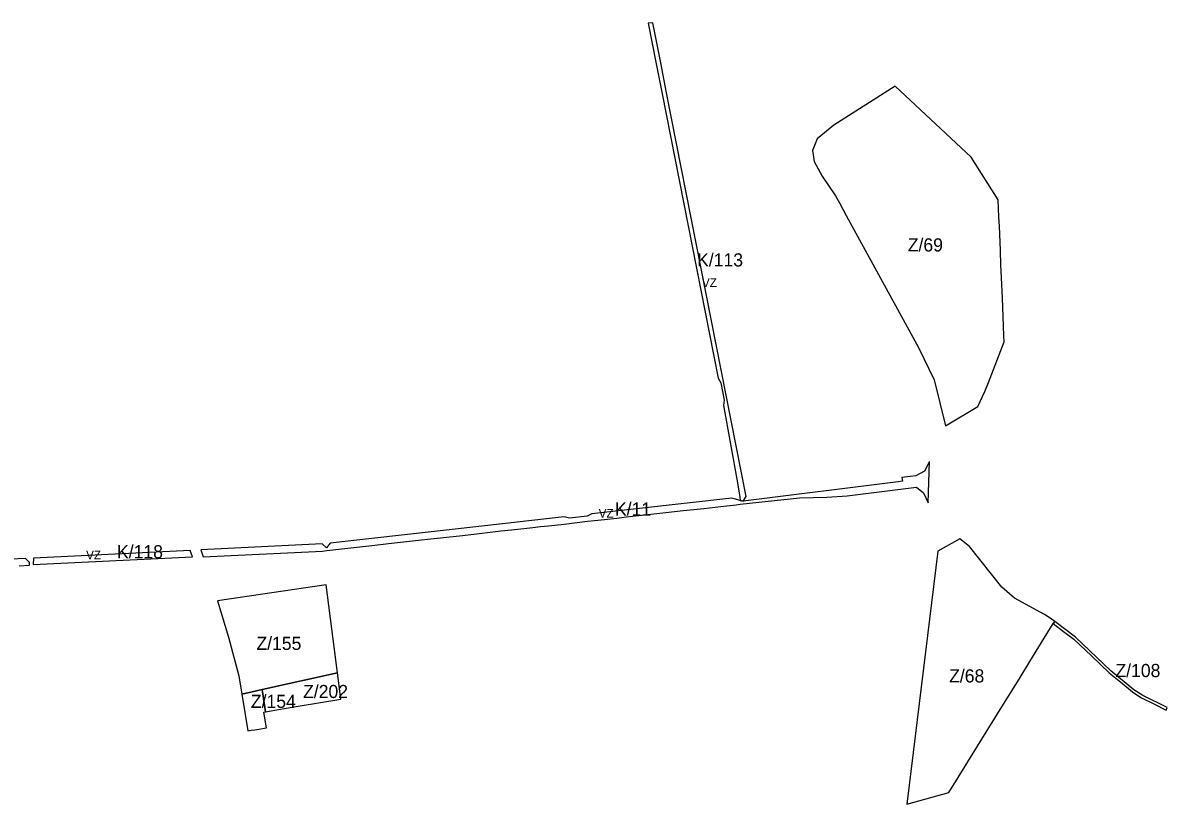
# Model space of a CAD drawing. Extents: x -521939 to -518034, y -1194984 to -1189555.
# Drawn here: x -519696 to -518391, y -1190882 to -1189991 of the extents above; entities that cross this region are included whole.
import ezdxf

# ---------------------------------------------------------------- set-up
doc = ezdxf.new("R2010")
doc.units = 0
for name, color, linetype in [('95420023', 7, 'Continuous'), ('96111023', 7, 'Continuous'), ('96202223', 7, 'Continuous')]:
    doc.layers.add(name, color=color, linetype=linetype)

msp = doc.modelspace()

# ---------------------------------------------------------------- linework, layer by layer
at = {"layer": '95420023'}
for points in [[(-518700.81, -1190062.95), (-518770.96, -1190107.15)], [(-518583.4, -1190192.5), (-518614.2, -1190143.77), (-518700.81, -1190062.95)], [(-518770.96, -1190107.15), (-518790.08, -1190122.73), (-518795.26, -1190136.18)], [(-518795.26, -1190136.18), (-518793.36, -1190148.8)], [(-518793.36, -1190148.8), (-518784.15, -1190165.5)], [(-518784.15, -1190165.5), (-518769.16, -1190188.04)], [(-518769.16, -1190188.04), (-518764.54, -1190195.99), (-518757.02, -1190210.42)], [(-518582.56, -1190212.26), (-518583.4, -1190192.5)], [(-518757.02, -1190210.42), (-518674.29, -1190361.03)], [(-518582.12, -1190222.61), (-518582.56, -1190212.26)], [(-518580.95, -1190250.13), (-518582.12, -1190222.61)], [(-518580.25, -1190266.63), (-518580.95, -1190250.13)], [(-518579.59, -1190281.03), (-518580.25, -1190266.63)], [(-518578.63, -1190304.8), (-518579.59, -1190281.03)], [(-518577.28, -1190336.35), (-518578.63, -1190304.8)], [(-518576.83, -1190347.45), (-518577.28, -1190336.35)], [(-518594.44, -1190400.79), (-518576.52, -1190354.3)], [(-518576.52, -1190354.3), (-518576.83, -1190347.45)], [(-518674.29, -1190361.03), (-518656.44, -1190397.83)], [(-518656.44, -1190397.83), (-518643.4, -1190450.09)], [(-518606.61, -1190428.32), (-518598.55, -1190411.07)], [(-518598.55, -1190411.07), (-518594.44, -1190400.79)], [(-518643.4, -1190450.09), (-518606.61, -1190428.32)], [(-518627.12, -1190579.12), (-518652.45, -1190593.34), (-518687.6, -1190881.68)], [(-518616.2, -1190587.89), (-518627.12, -1190579.12)], [(-518579.17, -1190634.29), (-518616.2, -1190587.89)], [(-519350.06, -1190631.54), (-519474.2, -1190649.71)], [(-519337.21, -1190732.05), (-519348.65, -1190643.36), (-519350.06, -1190631.54)], [(-518564.68, -1190646.91), (-518579.17, -1190634.29)], [(-518520.61, -1190672.06), (-518530.66, -1190665.45), (-518564.68, -1190646.91)], [(-519474.2, -1190649.71), (-519461.43, -1190691.22), (-519449.61, -1190735.43), (-519446.26, -1190756.2)], [(-518518.98, -1190673.29), (-518520.61, -1190672.06)], [(-518547.39, -1190719.17), (-518520.57, -1190675.85)], [(-518520.57, -1190675.85), (-518518.98, -1190673.29)], [(-518518.98, -1190673.29), (-518520.57, -1190675.85)], [(-518520.57, -1190675.85), (-518508.82, -1190684.74)], [(-518495.13, -1190691.35), (-518518.98, -1190673.29)], [(-518508.82, -1190684.74), (-518497.07, -1190693.64), (-518476.92, -1190712.71)], [(-518454.79, -1190729.54), (-518495.13, -1190691.35)], [(-518629.18, -1190851.22), (-518607.03, -1190815.46), (-518584.36, -1190778.86), (-518558.52, -1190737.14), (-518547.39, -1190719.17)], [(-518476.92, -1190712.71), (-518456.78, -1190731.79), (-518443.59, -1190742.68), (-518430.41, -1190753.58)], [(-519423.08, -1190751.07), (-519337.21, -1190732.05)], [(-519337.21, -1190732.05), (-519423.08, -1190751.07)], [(-519333.43, -1190761.83), (-519337.21, -1190732.05)], [(-518418.46, -1190757.75), (-518428.63, -1190751.16), (-518454.79, -1190729.54)], [(-519423.08, -1190751.07), (-519434.67, -1190753.64), (-519446.26, -1190756.2)], [(-519446.26, -1190756.2), (-519434.67, -1190753.64), (-519423.08, -1190751.07)], [(-519419.09, -1190776.27), (-519423.08, -1190751.07)], [(-519423.08, -1190751.07), (-519419.09, -1190776.27)], [(-519446.26, -1190756.2), (-519439.5, -1190798.18)], [(-519381.92, -1190770.01), (-519333.43, -1190761.83)], [(-518430.41, -1190753.58), (-518425.18, -1190756.97), (-518419.95, -1190760.36)], [(-518419.95, -1190760.36), (-518405.94, -1190767.38)], [(-518390.75, -1190771.64), (-518418.46, -1190757.75)], [(-519418.25, -1190794.59), (-519421.35, -1190776.66), (-519419.09, -1190776.27)], [(-519419.09, -1190776.27), (-519402.04, -1190773.36)], [(-519402.04, -1190773.36), (-519397.85, -1190772.66)], [(-519397.85, -1190772.66), (-519381.92, -1190770.01)], [(-518405.94, -1190767.38), (-518391.94, -1190774.4), (-518390.75, -1190771.64)], [(-519439.5, -1190798.18), (-519435.5, -1190797.51)], [(-519435.5, -1190797.51), (-519431.49, -1190796.83)], [(-519431.49, -1190796.83), (-519427.06, -1190796.08), (-519418.25, -1190794.59)], [(-518639.88, -1190868.49), (-518629.18, -1190851.22)], [(-518687.6, -1190881.68), (-518639.88, -1190868.49)]]:
    msp.add_lwpolyline(points, dxfattribs=at)
at = {"layer": '96111023'}
for points in [[(-518977.46, -1189990.66), (-518982.75, -1189991.08)], [(-518982.75, -1189991.08), (-518973.66, -1190037.25)], [(-518968.46, -1190036.36), (-518977.46, -1189990.66)], [(-518973.66, -1190037.25), (-518966.93, -1190071.42)], [(-518961.73, -1190070.59), (-518968.46, -1190036.36)], [(-518966.93, -1190071.42), (-518932.65, -1190245.48), (-518903.01, -1190395.98), (-518899.95, -1190401.14), (-518896.05, -1190420.93), (-518896.92, -1190426.87), (-518880.88, -1190515.41), (-518878.11, -1190531.65)], [(-518871.13, -1190530.87), (-518961.73, -1190070.59)], [(-518661.8, -1190490.82), (-518667.64, -1190501.77), (-518677.22, -1190507.17), (-518693.26, -1190509.28)], [(-518663.34, -1190537.95), (-518661.8, -1190490.82)], [(-518693.26, -1190509.28), (-518692.74, -1190513.36), (-518697.59, -1190513.92), (-518874.29, -1190536.33)], [(-518810.26, -1190532.19), (-518779.08, -1190531.51), (-518755.65, -1190530.1), (-518676.76, -1190520.2), (-518668.57, -1190526.63), (-518663.34, -1190537.95)], [(-518887.27, -1190532.68), (-519047.1, -1190550.59), (-519052.5, -1190553.21), (-519072.55, -1190555.45), (-519078.39, -1190554.09), (-519168.97, -1190564.24), (-519345.4, -1190584.01), (-519349.64, -1190589.23)], [(-518919.4, -1190544.34), (-518899.77, -1190542.15)], [(-518899.77, -1190542.15), (-518882.35, -1190540.18)], [(-518884.52, -1190533.45), (-518887.27, -1190532.68)], [(-518877.94, -1190535.3), (-518884.52, -1190533.45)], [(-518882.35, -1190540.18), (-518877.74, -1190539.66)], [(-518878.11, -1190531.65), (-518877.94, -1190535.3)], [(-518877.94, -1190535.3), (-518874.29, -1190536.33)], [(-518874.29, -1190536.33), (-518877.94, -1190535.3)], [(-518877.74, -1190539.66), (-518810.26, -1190532.19)], [(-518874.29, -1190536.33), (-518871.13, -1190530.87)], [(-519032.44, -1190556.99), (-519018.45, -1190555.44)], [(-519018.45, -1190555.44), (-519008.01, -1190554.21)], [(-519008.01, -1190554.21), (-518993.5, -1190552.64)], [(-518993.5, -1190552.64), (-518983.05, -1190551.46)], [(-518983.05, -1190551.46), (-518962.5, -1190549.15)], [(-518962.5, -1190549.15), (-518942.66, -1190546.94)], [(-518942.66, -1190546.94), (-518930.55, -1190545.57)], [(-518930.55, -1190545.57), (-518919.4, -1190544.34)], [(-519138.65, -1190568.93), (-519128.12, -1190567.71)], [(-519128.12, -1190567.71), (-519114.47, -1190566.26)], [(-519114.47, -1190566.26), (-519105.69, -1190565.24)], [(-519105.69, -1190565.24), (-519096.49, -1190564.2)], [(-519096.49, -1190564.2), (-519078.49, -1190562.26)], [(-519078.49, -1190562.26), (-519051.92, -1190559.12)], [(-519051.92, -1190559.12), (-519044.06, -1190558.34)], [(-519044.06, -1190558.34), (-519032.44, -1190556.99)], [(-519279.13, -1190584.54), (-519244.88, -1190580.73)], [(-519244.88, -1190580.73), (-519230.8, -1190579.2)], [(-519230.8, -1190579.2), (-519212.48, -1190577.18)], [(-519212.48, -1190577.18), (-519194.65, -1190575.18)], [(-519194.65, -1190575.18), (-519178.48, -1190573.43)], [(-519178.48, -1190573.43), (-519159.93, -1190571.22)], [(-519159.93, -1190571.22), (-519150.74, -1190570.16)], [(-519150.74, -1190570.16), (-519138.65, -1190568.93)], [(-519505.17, -1190592.27), (-519684.06, -1190601.07)], [(-519502.67, -1190599.7), (-519505.17, -1190592.27)], [(-519354.59, -1190584.65), (-519492.88, -1190591.75)], [(-519492.88, -1190591.75), (-519490.33, -1190599.63)], [(-519490.33, -1190599.63), (-519354.17, -1190593)], [(-519349.64, -1190589.23), (-519354.59, -1190584.65)], [(-519354.17, -1190593), (-519349.34, -1190592.5)], [(-519349.34, -1190592.5), (-519294.71, -1190586.4)], [(-519294.71, -1190586.4), (-519279.13, -1190584.54)], [(-519693.24, -1190601.52), (-519752.34, -1190604.4), (-519929.64, -1190613.04), (-519935.19, -1190615.32), (-519939.78, -1190615.54)], [(-519688.62, -1190605.97), (-519693.24, -1190601.52)], [(-519688.65, -1190609.3), (-519688.62, -1190605.97)], [(-519684.13, -1190608.58), (-519502.67, -1190599.7)], [(-519684.06, -1190601.07), (-519684.13, -1190608.58)], [(-519700.36, -1190609.88), (-519688.65, -1190609.3)]]:
    msp.add_lwpolyline(points, dxfattribs=at)
at = {"layer": '96202223'}
for points in [[(-518977.46, -1189990.66), (-518982.75, -1189991.08)], [(-518982.75, -1189991.08), (-518973.66, -1190037.25)], [(-518968.46, -1190036.36), (-518977.46, -1189990.66)], [(-518973.66, -1190037.25), (-518966.93, -1190071.42)], [(-518961.73, -1190070.59), (-518968.46, -1190036.36)], [(-518966.93, -1190071.42), (-518932.65, -1190245.48), (-518903.01, -1190395.98), (-518899.95, -1190401.14), (-518896.05, -1190420.93), (-518896.92, -1190426.87), (-518880.88, -1190515.41), (-518878.11, -1190531.65)], [(-518871.13, -1190530.87), (-518961.73, -1190070.59)], [(-518661.8, -1190490.82), (-518667.64, -1190501.77), (-518677.22, -1190507.17), (-518693.26, -1190509.28)], [(-518663.34, -1190537.95), (-518661.8, -1190490.82)], [(-518693.26, -1190509.28), (-518692.74, -1190513.36), (-518697.59, -1190513.92), (-518874.29, -1190536.33)], [(-518810.26, -1190532.19), (-518779.08, -1190531.51), (-518755.65, -1190530.1), (-518676.76, -1190520.2), (-518668.57, -1190526.63), (-518663.34, -1190537.95)], [(-518887.27, -1190532.68), (-519047.1, -1190550.59), (-519052.5, -1190553.21), (-519072.55, -1190555.45), (-519078.39, -1190554.09), (-519168.97, -1190564.24), (-519345.4, -1190584.01), (-519349.64, -1190589.23)], [(-518919.4, -1190544.34), (-518899.77, -1190542.15)], [(-518899.77, -1190542.15), (-518882.35, -1190540.18)], [(-518884.52, -1190533.45), (-518887.27, -1190532.68)], [(-518877.94, -1190535.3), (-518884.52, -1190533.45)], [(-518882.35, -1190540.18), (-518877.74, -1190539.66)], [(-518878.11, -1190531.65), (-518877.94, -1190535.3)], [(-518874.29, -1190536.33), (-518877.94, -1190535.3)], [(-518877.94, -1190535.3), (-518874.29, -1190536.33)], [(-518877.74, -1190539.66), (-518810.26, -1190532.19)], [(-518874.29, -1190536.33), (-518871.13, -1190530.87)], [(-519032.44, -1190556.99), (-519018.45, -1190555.44)], [(-519018.45, -1190555.44), (-519008.01, -1190554.21)], [(-519008.01, -1190554.21), (-518993.5, -1190552.64)], [(-518993.5, -1190552.64), (-518983.05, -1190551.46)], [(-518983.05, -1190551.46), (-518962.5, -1190549.15)], [(-518962.5, -1190549.15), (-518942.66, -1190546.94)], [(-518942.66, -1190546.94), (-518930.55, -1190545.57)], [(-518930.55, -1190545.57), (-518919.4, -1190544.34)], [(-519138.65, -1190568.93), (-519128.12, -1190567.71)], [(-519128.12, -1190567.71), (-519114.47, -1190566.26)], [(-519114.47, -1190566.26), (-519105.69, -1190565.24)], [(-519105.69, -1190565.24), (-519096.49, -1190564.2)], [(-519096.49, -1190564.2), (-519078.49, -1190562.26)], [(-519078.49, -1190562.26), (-519051.92, -1190559.12)], [(-519051.92, -1190559.12), (-519044.06, -1190558.34)], [(-519044.06, -1190558.34), (-519032.44, -1190556.99)], [(-519279.13, -1190584.54), (-519244.88, -1190580.73)], [(-519244.88, -1190580.73), (-519230.8, -1190579.2)], [(-519230.8, -1190579.2), (-519212.48, -1190577.18)], [(-519212.48, -1190577.18), (-519194.65, -1190575.18)], [(-519194.65, -1190575.18), (-519178.48, -1190573.43)], [(-519178.48, -1190573.43), (-519159.93, -1190571.22)], [(-519159.93, -1190571.22), (-519150.74, -1190570.16)], [(-519150.74, -1190570.16), (-519138.65, -1190568.93)], [(-519505.17, -1190592.27), (-519684.06, -1190601.07)], [(-519502.67, -1190599.7), (-519505.17, -1190592.27)], [(-519354.59, -1190584.65), (-519492.88, -1190591.75)], [(-519492.88, -1190591.75), (-519490.33, -1190599.63)], [(-519490.33, -1190599.63), (-519354.17, -1190593)], [(-519349.64, -1190589.23), (-519354.59, -1190584.65)], [(-519354.17, -1190593), (-519349.34, -1190592.5)], [(-519349.34, -1190592.5), (-519294.71, -1190586.4)], [(-519294.71, -1190586.4), (-519279.13, -1190584.54)], [(-519693.24, -1190601.52), (-519752.34, -1190604.4), (-519929.64, -1190613.04), (-519935.19, -1190615.32), (-519939.78, -1190615.54)], [(-519688.62, -1190605.97), (-519693.24, -1190601.52)], [(-519688.65, -1190609.3), (-519688.62, -1190605.97)], [(-519684.13, -1190608.58), (-519502.67, -1190599.7)], [(-519684.06, -1190601.07), (-519684.13, -1190608.58)], [(-519700.36, -1190609.88), (-519688.65, -1190609.3)]]:
    msp.add_lwpolyline(points, dxfattribs=at)

# ---------------------------------------------------------------- texts
at = {"layer": '95420023'}
msp.add_text('Z/69', height=15, dxfattribs=at).set_placement((-518686.62, -1190251.39))
for s, rotation, p in [('Z/155', 0, (-519429.66, -1190705.85)), ('Z/108', 360, (-518449.72, -1190736.81)), ('Z/68', 360, (-518639.44, -1190742.95)), ('Z/202', 360, (-519376.43, -1190760.72)), ('Z/154', 0, (-519435.98, -1190772))]:
    msp.add_text(s, height=15, rotation=rotation, dxfattribs=at).set_placement(p)
at = {"layer": '96111023'}
for s, p in [('K/113', (-518926.92, -1190268.48)), ('K/11', (-519020.68, -1190552.66)), ('K/118', (-519588.67, -1190601.32))]:
    msp.add_text(s, height=15, rotation=0, dxfattribs=at).set_placement(p)
at = {"layer": '96202223'}
for rotation, p in [(0, (-518921.42, -1190291.87)), (360, (-519039.22, -1190554.94)), (360, (-519623.94, -1190602.51))]:
    msp.add_text('VZ', height=10, rotation=rotation, dxfattribs=at).set_placement(p)

doc.saveas('drawing.dxf')
